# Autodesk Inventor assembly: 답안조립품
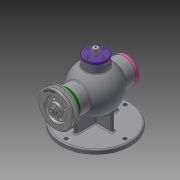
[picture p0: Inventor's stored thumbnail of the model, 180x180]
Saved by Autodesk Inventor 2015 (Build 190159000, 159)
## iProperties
Created: 2020-08
Part Number: 답안조립품
Document SubType Name: Assembly
Designer: 1019876
Author: 1019876
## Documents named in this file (18)
- C:\Users\1019876\Desktop\700806V1038\답안조립품.iam
- C:\Users\1019876\Desktop\700806V1038\V-벨트풀리.ipt
- C:\Users\1019876\Desktop\700806V1038\너트 M8.ipt
- C:\Users\1019876\Desktop\700806V1038\뒤커버.ipt
- C:\Users\1019876\Desktop\700806V1038\멈춤링 15x1.ipt
- C:\Users\1019876\Desktop\700806V1038\멈춤링 35x1.6.ipt
- 멈춤링 35x1.6.ipt
- C:\Users\1019876\Desktop\700806V1038\베어링 6202.ipt
- 베어링 6202.ipt
- C:\Users\1019876\Desktop\700806V1038\본체.ipt
- C:\Users\1019876\Desktop\700806V1038\볼트 M4.ipt
- C:\Users\1019876\Desktop\700806V1038\상부커버.ipt
- C:\Users\1019876\Desktop\700806V1038\슬라이드.ipt
- C:\Users\1019876\Desktop\700806V1038\앞커버.ipt
- C:\Users\1019876\Desktop\700806V1038\오일 실 15 30 7.ipt
- C:\Users\1019876\Desktop\700806V1038\칼라.ipt
- C:\Users\1019876\Desktop\700806V1038\키 3x3x12.ipt
- C:\Users\1019876\Desktop\700806V1038\편심축.ipt
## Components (1 placed, 1 different names)
1. V-벨트풀리:1 — 각도:2
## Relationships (1: Angle 1)
- 각도:2 [Angle]: V-벨트풀리:1
